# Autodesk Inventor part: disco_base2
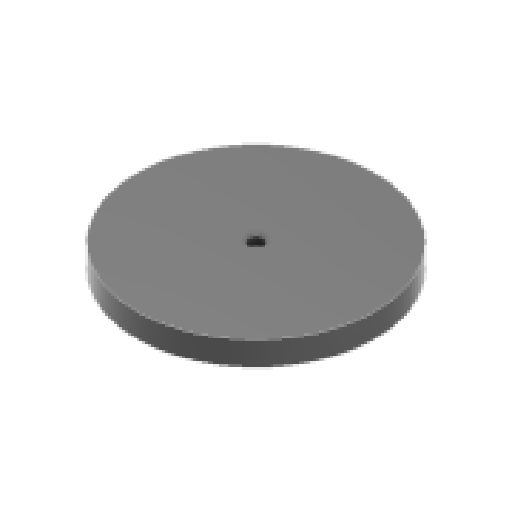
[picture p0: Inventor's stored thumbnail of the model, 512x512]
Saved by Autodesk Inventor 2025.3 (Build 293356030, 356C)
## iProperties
Created: 2026-03
Part Number: disco_base2
Material: Plastica ABS
Document SubType Name: Modeling
Designer: R5800u
Density: 1.06 g/cm^3
Appearance: Liscia - Nero
Author: R5800u
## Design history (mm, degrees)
sketch "Schizzo1"
  geometry: C1 r 50 at (0, 0); 1 further point
  constraints: 1 centre point, 1 coincident
  dimensions: "d0" = 100 diameter of C1
extrude "Estrusione1" new body sketch "Schizzo1" distance "d1" = 10; taper "d2" = 0 deg
sketch "Schizzo2"
  geometry: C1 r 50 at (0, 0) reference; 3 further points
  constraints: 1 coincident
hole "Foro1" sketch "Schizzo2" at (0, 0) diameter "d3" = 3.4; stored, may be unused: countersink angle "d7" = 82 deg, drill point angle "d9" = 118 deg; dims "d4" = 6, "d5" = 6.5, "d6" = 3.4, "d8" = 8
sketch "Schizzo4"
  geometry: C1 r 1.6 at (-55, 30) reference; C2 r 1.6 at (-55, -30) reference; C3 r 1.6 at (55, -30) reference; C4 r 1.6 at (55, 30) reference; 1 further point
hole "Foro2" sketch "Schizzo4" at (-55, 30), (-55, -30), (55, 30), (55, -30) diameter "d14" = 4.3; stored, may be unused: countersink angle "d18" = 90 deg, drill point angle "d20" = 118 deg; dims "d15" = 6, "d16" = 7.5, "d17" = 3, "d19" = 8
node "Solido1"
node "Riferimento5"
node "Riferimento6"
node "Riferimento7"
node "Riferimento8"
